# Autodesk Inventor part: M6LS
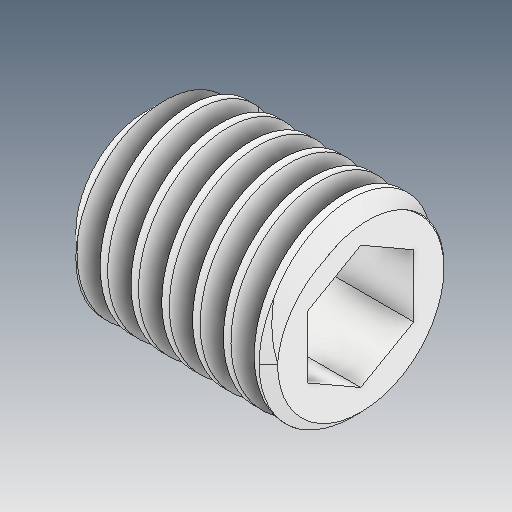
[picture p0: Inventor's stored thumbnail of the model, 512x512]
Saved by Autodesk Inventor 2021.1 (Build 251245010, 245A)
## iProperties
Created: 2021-05
Part Number: M6LS
Material: Ogólny
Document SubType Name: Modeling
Designer: user
Density: 1 g/cm^3
Appearance: Domyślna
Author: user
Revision Number: ÈÎºÎ
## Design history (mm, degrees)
feature "ÊäÈë1"
node "Bryła1"
